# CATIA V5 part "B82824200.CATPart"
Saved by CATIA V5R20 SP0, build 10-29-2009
Part number: B82824200
Revision: 5
Definition: design
Nomenclature: B82824200
Source: made
Description: NOT SPECIFIED
Bounding box of the stored display mesh (mm): x -14 to 14, y -14 to 14, z 0 to 200
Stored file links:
  C:\Users\Raffaele\Desktop\3D X SITO CF\BOLEX\7-PILLAR REF 828\B82824200.CATPart
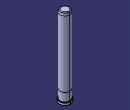
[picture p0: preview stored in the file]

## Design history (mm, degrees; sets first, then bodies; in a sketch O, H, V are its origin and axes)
Body1 "MANIFOLD_SOLID_BREP #450" (main body)
  Solid1: solid without history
